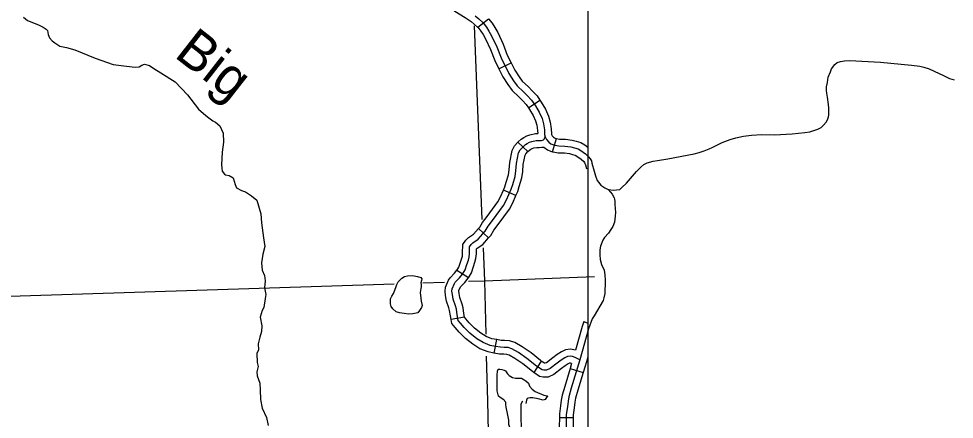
# Model space of a CAD drawing. Extents: x -5566 to 1759129, y -3726 to 731467.
# Drawn here: x -4493.8 to -4416.2, y 353.7 to 386.9 of the extents above; entities that cross this region are included whole.
import ezdxf

# ---------------------------------------------------------------- set-up
doc = ezdxf.new("R2010")
doc.units = 0
doc.layers.add('Default', color=7, linetype='Continuous')
doc.layers.add('R_No Plot', color=7, linetype='Continuous')

msp = doc.modelspace()

# ---------------------------------------------------------------- linework, layer by layer
at = {"layer": 'Default'}
for p, q in [((-4455.725, 386.208), (-4454.827, 386.909)), ((-4453.972, 382.749), (-4452.951, 383.255)), ((-4451.525, 379.534), (-4450.568, 380.152)), ((-4449.531, 375.886), (-4449.186, 376.971)), ((-4451.57, 375.887), (-4452.406, 376.661)), ((-4446.718, 374.478), (-4446.604, 374.508)), ((-4452.554, 372.254), (-4453.6, 372.706)), ((-4454.818, 368.745), (-4455.666, 369.505)), ((-4456.48, 365.441), (-4457.46, 366.022)), ((-4456.81, 362.18), (-4457.93, 361.976)), ((-4446.919, 361.799), (-4446.591, 361.679)), ((-4454.178, 360.311), (-4454.388, 359.192)), ((-4450.455, 358.527), (-4451.087, 357.58)), ((-4448.063, 357.923), (-4446.972, 357.592)), ((-4448.954, 353.863), (-4447.815, 353.854))]:
    msp.add_line(p, q, dxfattribs=at)
for points in [[(-4458.936, 388.388), (-4458.851, 388.317), (-4458.331, 387.95), (-4457.609, 387.527), (-4456.76, 387.017), (-4456.275, 386.687), (-4456.011, 386.467), (-4455.702, 386.178), (-4455.725, 386.208)], [(-4493.373, 387.05), (-4493.039, 386.774), (-4492.121, 386.404), (-4491.73, 386.195), (-4491.495, 386.054), (-4491.386, 385.939), (-4491.312, 385.589), (-4491.208, 385.328), (-4490.999, 385.083), (-4490.771, 384.917), (-4490.353, 384.634), (-4489.81, 384.509), (-4489.121, 384.342), (-4487.421, 383.632), (-4485.939, 383.11), (-4484.844, 382.985), (-4484.124, 382.881), (-4483.779, 382.912), (-4483.571, 383.069), (-4483.331, 383.152), (-4482.924, 383.037), (-4482.559, 382.776), (-4481.985, 382.411), (-4480.81, 381.681), (-4479.783, 380.605), (-4478.858, 379.417), (-4478.254, 378.898), (-4478.011, 378.686), (-4477.676, 378.446), (-4477.452, 378.34), (-4477.099, 378.025), (-4476.811, 377.426), (-4476.8, 376.687), (-4476.898, 375.853), (-4476.951, 374.791), (-4476.909, 374.267), (-4476.703, 374.031), (-4476.617, 373.965), (-4476.319, 373.907), (-4475.993, 373.706), (-4475.813, 373.163), (-4475.72, 372.9), (-4475.302, 372.671), (-4474.957, 372.562), (-4474.482, 372.236), (-4474.035, 371.863), (-4473.691, 370.74), (-4473.656, 369.994), (-4473.481, 368.743), (-4473.365, 368.039), (-4473.539, 367.392), (-4473.649, 366.679), (-4473.574, 366.065), (-4473.39, 365.614), (-4473.344, 365.166), (-4473.399, 364.592), (-4473.288, 364.055), (-4473.352, 363.718), (-4473.446, 362.96), (-4473.597, 362.726), (-4473.75, 362.156), (-4473.619, 361.46), (-4473.64, 360.986), (-4473.789, 360.501), (-4473.921, 359.955), (-4473.903, 359.46), (-4474.028, 359.143), (-4474.001, 358.405), (-4473.921, 358.08), (-4474.019, 357.642), (-4474.007, 357.315), (-4473.779, 356.683), (-4473.752, 356.15), (-4473.722, 355.328), (-4473.591, 354.632), (-4473.236, 353.852), (-4473.098, 353.186)], [(-4455.931, 387.142), (-4455.634, 386.894), (-4455.28, 386.564), (-4455.005, 386.211), (-4454.799, 385.889), (-4454.569, 385.501), (-4454.145, 384.573), (-4453.792, 383.669), (-4453.151, 382.375), (-4452.766, 381.767), (-4452.455, 381.352), (-4451.925, 380.85), (-4451.612, 380.536), (-4451.253, 380.162), (-4450.939, 379.676), (-4450.618, 379.153), (-4450.393, 378.633), (-4450.274, 378.199), (-4450.198, 377.708), (-4450.177, 377.31), (-4450.147, 377.119), (-4450.027, 376.884), (-4449.84, 376.674), (-4449.653, 376.532), (-4449.496, 376.472), (-4449.332, 376.42), (-4449.003, 376.364), (-4448.495, 376.353), (-4448.017, 376.286), (-4447.71, 376.211), (-4447.411, 376.12), (-4447.18, 375.979), (-4446.798, 375.694), (-4446.537, 375.462), (-4446.395, 375.299), (-4446.305, 375.119), (-4446.253, 374.947), (-4446.073, 374.266), (-4445.961, 373.892), (-4445.812, 373.488), (-4445.715, 373.346), (-4445.513, 373.122), (-4445.177, 372.883), (-4444.908, 372.763)], [(-4454.827, 386.909), (-4454.539, 386.54), (-4454.314, 386.188), (-4454.063, 385.765), (-4453.62, 384.795), (-4453.271, 383.899), (-4452.951, 383.255)], [(-4456.025, 386.305), (-4455.378, 370.276)], [(-4455.725, 386.208), (-4455.47, 385.881), (-4455.284, 385.591), (-4455.074, 385.236), (-4454.67, 384.351), (-4454.314, 383.439), (-4453.972, 382.749)], [(-4452.951, 383.255), (-4452.654, 382.655), (-4452.297, 382.091), (-4452.028, 381.732), (-4451.528, 381.258), (-4451.205, 380.934), (-4450.804, 380.517), (-4450.568, 380.152)], [(-4427.539, 377.748), (-4427.248, 377.904), (-4427.058, 378.086), (-4426.854, 378.345), (-4426.748, 378.526), (-4426.657, 378.774), (-4426.627, 378.924), (-4426.614, 379.219), (-4426.632, 379.5), (-4426.66, 379.788), (-4426.732, 380.407), (-4426.803, 380.745), (-4426.814, 380.944), (-4426.814, 381.256), (-4426.737, 381.62), (-4426.671, 382.062), (-4426.494, 382.511), (-4426.395, 382.765), (-4426.141, 383.106), (-4425.943, 383.272), (-4425.655, 383.357), (-4425.325, 383.416), (-4424.914, 383.437), (-4422.35, 383.316), (-4419.78, 383.051), (-4419.075, 382.977), (-4418.753, 382.897), (-4418.322, 382.745), (-4417.906, 382.562), (-4417.118, 382.209), (-4416.631, 381.958), (-4416.434, 381.889), (-4416.228, 381.831)], [(-4453.972, 382.749), (-4453.648, 382.096), (-4453.235, 381.444), (-4452.882, 380.971), (-4452.323, 380.442), (-4452.018, 380.137), (-4451.702, 379.807), (-4451.525, 379.534)], [(-4450.568, 380.152), (-4450.457, 379.98), (-4450.111, 379.416), (-4449.855, 378.823), (-4449.716, 378.319), (-4449.631, 377.767), (-4449.609, 377.369), (-4449.598, 377.297), (-4449.553, 377.208), (-4449.452, 377.094), (-4449.374, 377.035), (-4449.309, 377.01), (-4449.186, 376.971)], [(-4451.525, 379.534), (-4451.421, 379.373), (-4451.124, 378.89), (-4450.932, 378.444), (-4450.832, 378.08), (-4450.765, 377.649), (-4450.751, 377.38)], [(-4444.908, 372.763), (-4444.444, 372.696), (-4444.213, 372.711), (-4443.936, 372.763), (-4443.772, 372.905), (-4443.383, 373.264), (-4442.571, 374.241), (-4442.21, 374.6), (-4441.948, 374.827), (-4441.671, 374.97), (-4441.181, 375.094), (-4440.815, 375.142), (-4439.979, 375.282), (-4437.794, 375.701), (-4437.375, 375.812), (-4436.945, 375.944), (-4436.546, 376.109), (-4436.305, 376.22), (-4435.455, 376.639), (-4434.804, 376.904), (-4434.338, 377.046), (-4433.698, 377.183), (-4433.032, 377.245), (-4432.176, 377.322), (-4431.117, 377.294), (-4429.666, 377.374), (-4428.622, 377.473), (-4428.191, 377.534), (-4427.539, 377.748)], [(-4456.622, 366.539), (-4456.497, 366.9), (-4456.436, 367.131), (-4456.402, 367.445), (-4456.401, 368.01), (-4456.269, 368.194), (-4456.129, 368.333), (-4455.688, 368.627), (-4455.099, 369.285), (-4454.849, 369.698), (-4454.494, 370.175), (-4453.583, 371.428), (-4453.334, 371.886), (-4452.949, 372.777), (-4452.827, 373.177), (-4452.623, 373.833), (-4452.557, 374.307), (-4452.51, 374.911), (-4452.337, 375.786), (-4452.202, 376.043), (-4451.969, 376.295), (-4451.776, 376.472), (-4451.615, 376.577), (-4451.44, 376.663), (-4451.234, 376.742), (-4450.875, 376.813), (-4450.651, 376.809), (-4450.438, 376.82), (-4450.345, 376.828), (-4450.285, 376.869), (-4450.229, 376.925), (-4450.203, 376.992), (-4450.147, 377.119)], [(-4452.406, 376.661), (-4452.371, 376.699), (-4452.127, 376.924), (-4451.897, 377.073), (-4451.667, 377.186), (-4451.392, 377.291), (-4450.926, 377.383), (-4450.751, 377.38)], [(-4449.197, 376.975), (-4448.949, 376.933), (-4448.449, 376.921), (-4447.909, 376.846), (-4447.56, 376.76), (-4447.177, 376.644), (-4446.86, 376.451), (-4446.605, 376.259), (-4446.605, 376.259), (-4446.605, 376.259), (-4446.605, 376.259), (-4446.605, 376.259), (-4446.605, 376.259)], [(-4453.6, 372.706), (-4453.484, 372.973), (-4453.371, 373.345), (-4453.181, 373.957), (-4453.123, 374.369), (-4453.076, 374.989), (-4452.88, 375.978), (-4452.671, 376.375), (-4452.406, 376.661)], [(-4451.57, 375.887), (-4451.566, 375.891), (-4451.425, 376.021), (-4451.334, 376.081), (-4451.212, 376.14), (-4451.076, 376.192), (-4450.824, 376.242), (-4450.641, 376.239), (-4450.4, 376.252), (-4450.242, 376.264)], [(-4450.242, 376.264), (-4449.933, 376.029), (-4449.684, 375.935), (-4449.531, 375.886)], [(-4452.554, 372.254), (-4452.413, 372.58), (-4452.282, 373.01), (-4452.065, 373.708), (-4451.99, 374.246), (-4451.945, 374.834), (-4451.795, 375.594), (-4451.733, 375.711), (-4451.57, 375.887)], [(-4449.531, 375.886), (-4449.467, 375.865), (-4449.058, 375.796), (-4448.541, 375.784), (-4448.124, 375.725), (-4447.86, 375.661), (-4447.646, 375.596), (-4447.499, 375.507), (-4447.158, 375.252), (-4446.943, 375.061), (-4446.872, 374.98), (-4446.836, 374.907), (-4446.801, 374.792), (-4446.718, 374.478)], [(-4455.666, 369.505), (-4455.559, 369.625), (-4455.322, 370.016), (-4454.953, 370.513), (-4454.066, 371.732), (-4453.847, 372.136), (-4453.6, 372.706)], [(-4454.818, 368.745), (-4454.64, 368.944), (-4454.375, 369.379), (-4454.035, 369.838), (-4453.1, 371.123), (-4452.821, 371.637), (-4452.554, 372.254)], [(-4444.908, 372.763), (-4444.713, 372.539), (-4444.579, 372.367), (-4444.407, 372.068), (-4444.384, 371.948), (-4444.362, 371.761), (-4444.347, 371.53), (-4444.34, 371.156), (-4444.31, 370.875), (-4444.325, 370.538), (-4444.377, 370.037), (-4444.526, 369.693), (-4444.691, 369.424), (-4444.893, 369.132), (-4445.207, 368.781), (-4445.363, 368.542), (-4445.55, 368.042), (-4445.595, 367.758), (-4445.607, 367.341), (-4445.57, 366.946), (-4445.457, 366.531), (-4445.255, 366.057), (-4445.196, 365.686), (-4445.169, 365.245), (-4445.169, 364.766), (-4445.177, 364.519), (-4445.199, 364.116), (-4445.274, 363.779), (-4445.34, 363.539), (-4446.081, 362.269), (-4446.23, 362.022), (-4446.529, 361.207), (-4447.252, 358.633), (-4447.969, 356.269), (-4448.164, 355.575), (-4448.233, 355.211), (-4448.293, 354.733), (-4448.383, 354.108), (-4448.391, 353.087)], [(-4457.46, 366.022), (-4457.286, 366.316), (-4457.163, 366.716), (-4457.042, 367.065), (-4456.998, 367.235), (-4456.972, 367.477), (-4456.97, 368.194), (-4456.704, 368.564), (-4456.492, 368.776), (-4456.064, 369.061), (-4455.666, 369.505)], [(-4456.48, 365.441), (-4456.237, 365.852), (-4456.08, 366.363), (-4455.951, 366.734), (-4455.875, 367.028), (-4455.833, 367.414), (-4455.832, 367.825), (-4455.766, 367.891), (-4455.312, 368.194), (-4454.818, 368.745)], [(-4455.283, 367.909), (-4455.173, 365.185)], [(-4457.93, 361.976), (-4457.984, 362.272), (-4458.052, 362.706), (-4458.11, 362.941), (-4458.298, 363.503), (-4458.39, 363.969), (-4458.429, 364.33), (-4458.391, 364.658), (-4458.158, 365.244), (-4458.016, 365.428), (-4457.648, 365.807), (-4457.441, 366.055), (-4457.46, 366.022)], [(-4447.252, 358.633), (-4447.647, 358.816), (-4447.858, 358.901), (-4448.055, 358.943), (-4448.281, 358.901), (-4448.506, 358.802), (-4448.816, 358.605), (-4449.14, 358.351), (-4449.717, 357.9), (-4450.013, 357.773), (-4450.239, 357.773), (-4450.394, 357.801), (-4450.858, 358.111), (-4451.647, 358.746), (-4452.337, 359.225), (-4452.887, 359.535), (-4453.211, 359.647), (-4453.521, 359.661), (-4453.845, 359.676), (-4454.253, 359.746), (-4454.704, 359.831), (-4455.281, 360.056), (-4455.788, 360.38), (-4456.366, 360.831), (-4456.845, 361.31), (-4457.141, 361.662), (-4457.338, 361.902), (-4457.422, 362.367), (-4457.493, 362.818), (-4457.562, 363.1), (-4457.746, 363.649), (-4457.827, 364.055), (-4457.856, 364.327), (-4457.834, 364.518), (-4457.658, 364.96), (-4457.584, 365.055), (-4457.225, 365.425), (-4456.974, 365.724), (-4456.761, 366.084), (-4456.622, 366.539)], [(-4462.592, 364.396), (-4462.493, 364.706), (-4462.437, 364.875), (-4462.31, 365.101), (-4462.014, 365.397), (-4461.803, 365.552), (-4461.55, 365.594), (-4461.141, 365.622), (-4460.704, 365.552), (-4460.451, 365.467), (-4460.352, 365.34), (-4460.38, 365.199), (-4460.437, 365.016), (-4460.423, 364.875), (-4460.423, 364.692), (-4460.451, 364.537), (-4460.493, 364.213)], [(-4456.81, 362.18), (-4456.861, 362.462), (-4456.934, 362.93), (-4457.015, 363.258), (-4457.195, 363.796), (-4457.263, 364.141), (-4457.283, 364.325), (-4457.277, 364.377), (-4457.158, 364.675), (-4457.153, 364.682), (-4456.802, 365.043), (-4456.508, 365.394), (-4456.48, 365.441)], [(-4455.173, 365.185), (-4446.054, 365.547)], [(-4494.509, 363.907), (-4462.64, 364.942)], [(-4460.28, 365.019), (-4458.476, 365.077)], [(-4456.501, 365.141), (-4455.173, 365.185)], [(-4455.173, 365.185), (-4455.058, 360.769)], [(-4460.493, 364.213), (-4460.437, 363.734), (-4460.409, 363.48), (-4460.324, 363.142), (-4460.38, 362.959), (-4460.535, 362.719), (-4460.69, 362.536), (-4461.099, 362.452), (-4461.451, 362.423), (-4461.817, 362.466), (-4462.212, 362.536), (-4462.493, 362.621), (-4462.747, 362.846), (-4462.888, 363.043), (-4462.958, 363.269), (-4462.958, 363.494), (-4462.944, 363.692), (-4462.846, 363.903), (-4462.691, 364.128), (-4462.592, 364.396)], [(-4454.178, 360.311), (-4454.546, 360.381), (-4455.022, 360.566), (-4455.459, 360.846), (-4455.988, 361.258), (-4456.425, 361.695), (-4456.703, 362.027), (-4456.804, 362.15), (-4456.81, 362.18)], [(-4454.388, 359.192), (-4454.861, 359.281), (-4455.541, 359.546), (-4456.118, 359.915), (-4456.744, 360.404), (-4457.265, 360.925), (-4457.579, 361.298), (-4457.872, 361.654), (-4457.93, 361.976)], [(-4446.919, 361.799), (-4447.072, 361.383), (-4447.62, 359.432)], [(-4450.455, 358.527), (-4450.521, 358.571), (-4451.306, 359.202), (-4452.034, 359.708), (-4452.651, 360.056), (-4453.102, 360.213), (-4453.495, 360.23), (-4453.784, 360.243), (-4454.152, 360.307), (-4454.178, 360.311)], [(-4451.087, 357.58), (-4451.195, 357.652), (-4451.988, 358.289), (-4452.64, 358.742), (-4453.122, 359.014), (-4453.32, 359.082), (-4453.546, 359.092), (-4453.906, 359.108), (-4454.354, 359.185), (-4454.388, 359.192)], [(-4447.62, 359.432), (-4448.048, 359.524), (-4448.449, 359.448), (-4448.775, 359.306), (-4449.145, 359.07), (-4449.491, 358.8), (-4450.01, 358.394), (-4450.13, 358.343), (-4450.179, 358.343), (-4450.455, 358.527)], [(-4455.01, 358.933), (-4454.913, 355.227), (-4454.699, 345.015), (-4454.604, 343.131)], [(-4447.942, 358.321), (-4448.025, 358.354), (-4448.063, 358.362), (-4448.112, 358.353), (-4448.237, 358.298), (-4448.487, 358.139), (-4448.789, 357.902), (-4449.425, 357.406), (-4449.896, 357.204), (-4450.29, 357.204), (-4450.611, 357.262), (-4451.087, 357.58)], [(-4447.942, 358.321), (-4448.063, 357.923)], [(-4446.6, 358.843), (-4446.6, 358.843), (-4446.706, 358.473), (-4446.972, 357.592)], [(-4453.567, 355.313), (-4453.851, 355.507), (-4454.001, 355.627), (-4454.12, 356.06), (-4454.12, 356.883), (-4454.12, 357.361), (-4454.091, 357.69), (-4454.016, 357.855), (-4453.881, 357.855), (-4453.717, 357.84), (-4453.537, 357.78), (-4453.433, 357.705), (-4453.268, 357.466), (-4453.104, 357.331), (-4452.835, 357.152), (-4452.596, 357.122), (-4452.282, 357.122), (-4452.103, 357.122), (-4451.744, 356.898), (-4451.505, 356.688), (-4451.445, 356.434), (-4451.221, 356.21), (-4450.952, 356), (-4450.249, 355.701), (-4449.965, 355.642), (-4449.92, 355.582), (-4450.01, 355.507), (-4450.129, 355.342), (-4450.294, 355.298), (-4450.727, 355.402), (-4451.161, 355.492), (-4451.4, 355.492), (-4451.624, 355.417), (-4451.684, 355.283), (-4451.729, 355.014)], [(-4448.063, 357.923), (-4448.515, 356.428), (-4448.719, 355.705), (-4448.796, 355.3), (-4448.858, 354.809), (-4448.952, 354.151), (-4448.954, 353.863)], [(-4446.972, 357.592), (-4447.422, 356.109), (-4447.609, 355.444), (-4447.67, 355.122), (-4447.729, 354.657), (-4447.814, 354.066), (-4447.815, 353.854)], [(-4452.013, 355.208), (-4452.162, 354.954), (-4452.162, 354.61), (-4452.147, 354.131), (-4452.147, 353.713), (-4452.132, 353.159), (-4452.222, 352.486), (-4452.342, 352.113), (-4452.461, 351.754), (-4452.581, 351.694), (-4452.656, 351.799), (-4452.835, 352.382), (-4452.91, 352.696), (-4453.029, 352.95), (-4453.134, 353.264), (-4453.134, 353.623), (-4453.268, 354.191), (-4453.358, 354.714), (-4453.388, 354.924), (-4453.388, 355.133), (-4453.612, 355.357), (-4453.851, 355.507)], [(-4448.954, 353.863), (-4448.961, 353.079), (-4448.939, 352.486), (-4448.788, 351.631), (-4448.664, 351.009), (-4448.479, 350.236), (-4448.416, 349.816)], [(-4447.815, 353.854), (-4447.822, 353.095), (-4447.804, 352.607), (-4447.668, 351.841), (-4447.551, 351.253), (-4447.36, 350.454), (-4447.289, 349.985)]]:
    msp.add_lwpolyline(points, dxfattribs=at)
at = {"layer": 'R_No Plot'}
msp.add_lwpolyline([(-5018.988, 168.239), (-5018.988, 511.979), (-4446.603, 511.979), (-4446.603, 160.504), (-4913.433, 160.504)], dxfattribs=at)

# ---------------------------------------------------------------- texts
at = {"layer": 'Default'}
msp.add_text('Big', height=3.2048, rotation=321.99064, dxfattribs=at).set_placement((-4480.969, 383.805))

doc.saveas('drawing.dxf')
